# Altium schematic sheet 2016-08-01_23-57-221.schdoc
size 440 x 220 mm; SheetNumber: 1; SheetTotal: 1
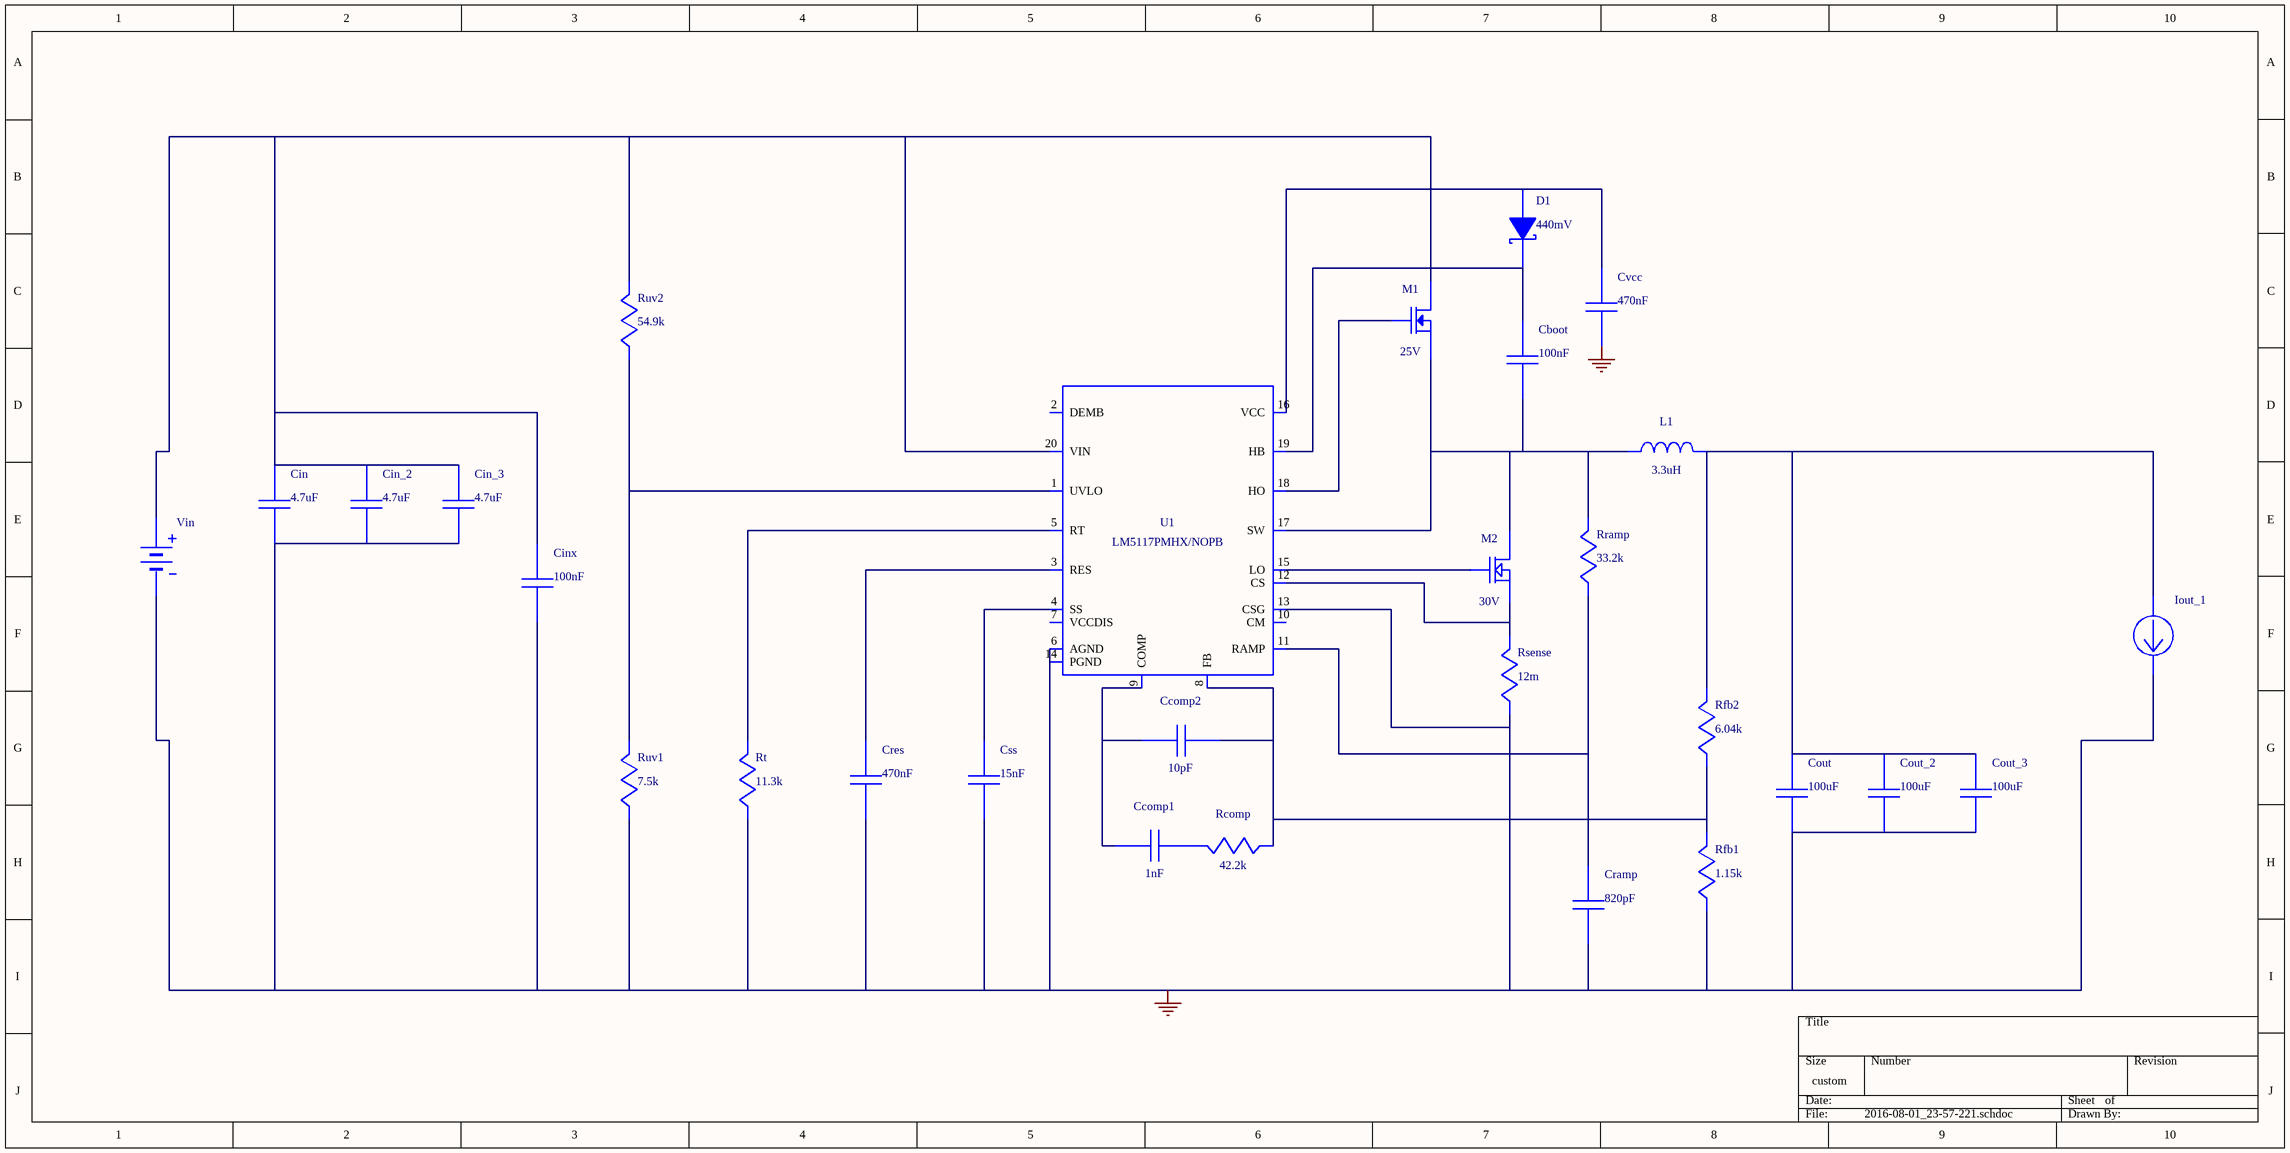
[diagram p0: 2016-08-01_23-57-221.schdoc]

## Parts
Cboot  value 100nF  (hidden comment: GRM155R61A104KA01D)
Ccomp1  value 1nF  (hidden comment: CL21C102JBCNFNC)
Ccomp2  value 10pF  (hidden comment: C0805C100K5GACTU)
Cin  value 4.7uF  (hidden comment: GRM21BR61E475MA12L)
Cin_2  value 4.7uF  (hidden comment: GRM21BR61E475MA12L)
Cin_3  value 4.7uF  (hidden comment: GRM21BR61E475MA12L)
Cinx  value 100nF  (hidden comment: 08053C104KAT2A)
Cout  value 100uF  (hidden comment: GRM31CR60J107ME39L)
Cout_2  value 100uF  (hidden comment: GRM31CR60J107ME39L)
Cout_3  value 100uF  (hidden comment: GRM31CR60J107ME39L)
Cramp  value 820pF  (hidden comment: CC0805KRX7R9BB821)
Cres  value 470nF  (hidden comment: GRM155C80J474KE19D)
Css  value 15nF  (hidden comment: CC0805KRX7R9BB153)
Cvcc  value 470nF  (hidden comment: GRM155R61A474KE15D)
D1  value 440mV  (hidden comment: CD0603-B0130L)
Iout_1  WB_CURRENT_LOAD  (value not drawn)
L1  value 3.3uH  (hidden comment: IHLP3232DZER3R3M11)
M1  value 25V  (hidden comment: CSD16409Q3)
M2  value 30V  (hidden comment: CSD17577Q3A)
Rcomp  value 42.2k  (hidden comment: CRCW040242K2FKED)
Rfb1  value 1.15k  (hidden comment: CRCW04021K15FKED)
Rfb2  value 6.04k  (hidden comment: CRCW04026K04FKED)
Rramp  value 33.2k  (hidden comment: CRCW040233K2FKED)
Rsense  value 12m  (hidden comment: CSR1206FK12L0)
Rt  value 11.3k  (hidden comment: CRCW040211K3FKED)
Ruv1  value 7.5k  (hidden comment: CRCW04027K50FKED)
Ruv2  value 54.9k  (hidden comment: CRCW040254K9FKED)
U1  LM5117PMHX/NOPB
Vin  WB_BATTERY  (value not drawn)

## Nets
0: Cin.2 Cin_2.2 Cin_3.2 Cinx.2 Cout.2 Cout_2.2 Cout_3.2 Cramp.2 Cres.2 Css.2 Cvcc.2 Iout_1.2(-) Rfb1.2 Rsense.2 Rt.2 Ruv1.2 U1.6(AGND) U1.13(CSG) U1.14(PGND) U1.21(EP) Vin.2(-)
NetCboot_1: Cboot.1 D1.1(K) U1.19(HB)
NetCboot_2: Cboot.2 L1.1 M1.1(Source) M1.2(Source) M1.3(Source) M2.5(Drain) M2.6(Drain) M2.7(Drain) M2.8(Drain) M2.9(Drain) Rramp.1 U1.17(SW)
NetCcomp1_1: Ccomp1.1 Ccomp2.1 U1.9(COMP)
NetCcomp1_2: Ccomp1.2 Rcomp.1
NetCcomp2_2: Ccomp2.2 Rcomp.2 Rfb1.1 Rfb2.2 U1.8(FB)
NetCin_1: Cin.1 Cin_2.1 Cin_3.1 Cinx.1 M1.5(Drain) M1.6(Drain) M1.7(Drain) M1.8(Drain) M1.9(Drain) Ruv2.1 U1.20(VIN) Vin.1(+)
NetCout_1: Cout.1 Cout_2.1 Cout_3.1 Iout_1.1(+) L1.2 Rfb2.1
NetCramp_1: Cramp.1 Rramp.2 U1.11(RAMP)
NetCres_1: Cres.1 U1.3(RES)
NetCss_1: Css.1 U1.4(SS)
NetCvcc_1: Cvcc.1 D1.2(A) U1.16(VCC)
NetM1_4: M1.4(Gate) U1.18(HO)
NetM2_1: M2.1(Source) M2.2(Source) M2.3(Source) Rsense.1 U1.12(CS)
NetM2_4: M2.4(Gate) U1.15(LO)
NetRt_1: Rt.1 U1.5(RT)
NetRuv1_1: Ruv1.1 Ruv2.2 U1.1(UVLO)

Not connected (* = marked no-connect by the designer): U1 2(DEMB) 7(VCCDIS) 10(CM)

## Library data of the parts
Cboot = GRM155R61A104KA01D: GRM155R61A104KA0; Manufacturer Name: MuRata
Ccomp1 = CL21C102JBCNFNC: Manufacturer Name: Samsung Electro-Mechanics
Ccomp2 = C0805C100K5GACTU: Manufacturer Name: Kemet
Cin Cin_2 Cin_3 = GRM21BR61E475MA12L: GRM21BR61E475MA1; Manufacturer Name: MuRata
Cinx = 08053C104KAT2A: Manufacturer Name: AVX
Cout Cout_2 Cout_3 = GRM31CR60J107ME39L: GRM31CR60J107ME3; Manufacturer Name: MuRata
Cramp = CC0805KRX7R9BB821: CC0805KRX7R9BB82; Manufacturer Name: Yageo America
Cres = GRM155C80J474KE19D: GRM155C80J474KE1; Manufacturer Name: MuRata
Css = CC0805KRX7R9BB153: CC0805KRX7R9BB15; Manufacturer Name: Yageo America
Cvcc = GRM155R61A474KE15D: GRM155R61A474KE1; Manufacturer Name: MuRata
D1 = CD0603-B0130L: Manufacturer Name: Bourns
L1 = IHLP3232DZER3R3M11: Unknown; Manufacturer Name: Vishay-Dale
M1 = CSD16409Q3: Manufacturer Name: Texas Instruments
M2 = CSD17577Q3A: Manufacturer Name: Texas Instruments
Rcomp = CRCW040242K2FKED: Manufacturer Name: Vishay-Dale
Rfb1 = CRCW04021K15FKED: Manufacturer Name: Vishay-Dale
Rfb2 = CRCW04026K04FKED: Manufacturer Name: Vishay-Dale
Rramp = CRCW040233K2FKED: Manufacturer Name: Vishay-Dale
Rsense = CSR1206FK12L0: Manufacturer Name: Stackpole Electronics Inc
Rt = CRCW040211K3FKED: Manufacturer Name: Vishay-Dale
Ruv1 = CRCW04027K50FKED: Manufacturer Name: Vishay-Dale
Ruv2 = CRCW040254K9FKED: Manufacturer Name: Vishay-Dale
U1 = LM5117PMHX/NOPB: Manufacturer Name: Texas Instruments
